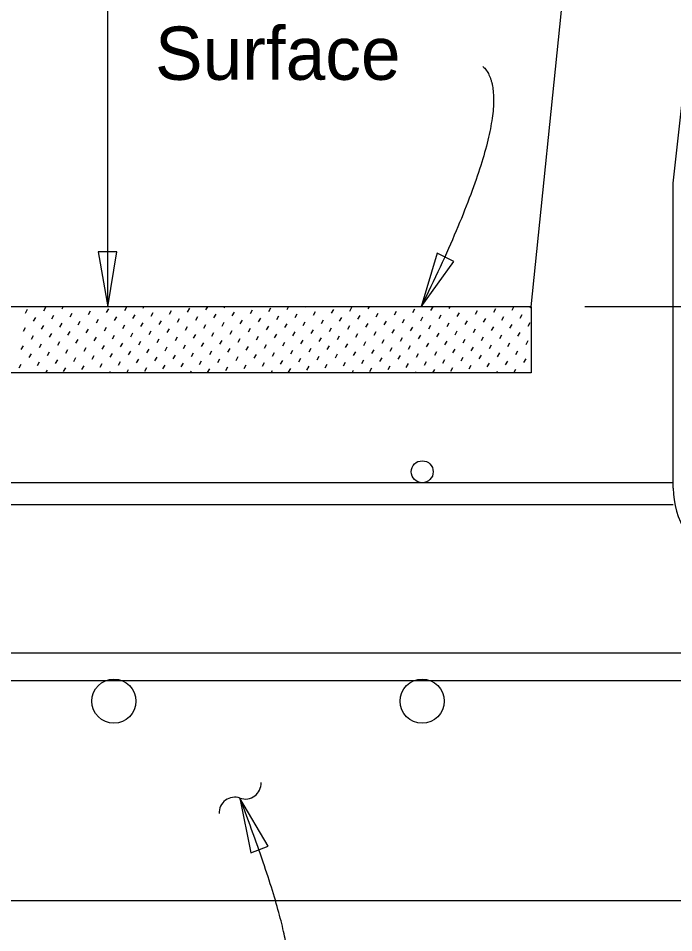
# Model space of a CAD drawing. Extents: x 130539.2 to 130573.7, y 88651.8 to 88671.1.
# Drawn here: x 130553.108 to 130554.348, y 88663.113 to 88664.844 of the extents above; entities that cross this region are included whole.
import ezdxf

# ---------------------------------------------------------------- set-up
doc = ezdxf.new("R2010")
doc.units = 0
for name, color, linetype in [('Dimension', 7, 'Continuous'), ('Miscellaneous', 7, 'Continuous'), ('Rebar', 7, 'Continuous'), ('Rebar_h', 7, 'Continuous'), ('TrafBarrierConc', 7, 'Continuous')]:
    doc.layers.add(name, color=color, linetype=linetype)

msp = doc.modelspace()

# ---------------------------------------------------------------- linework, layer by layer
at = {"layer": 'Dimension'}
msp.add_line((130553.277, 88664.2981), (130553.277, 88666.9647), dxfattribs=at)
for points in [[(130553.277, 88664.2981), (130553.2946, 88664.4022), (130553.2593, 88664.4022)], [(130553.8701, 88664.2981), (130553.9319, 88664.3837), (130553.9002, 88664.3993)], [(130553.5272, 88663.3673), (130553.5479, 88663.2638), (130553.5808, 88663.2764)]]:
    msp.add_lwpolyline(points, close=True, dxfattribs=at)
for centre, start, end in [((130553.5374, 88663.3956), 250.679, 2.4062), ((130553.5176, 88663.3394), 70.679, 182.4062)]:
    msp.add_arc(centre, 0.0298, start, end, dxfattribs=at)
for points in [[(130553.987, 88664.753), (130554.0597, 88664.6838), (130553.8701, 88664.2981)], [(130553.3789, 88662.9747), (130553.4967, 88662.9747), (130553.6188, 88662.9747), (130553.6188, 88663.1274), (130553.5272, 88663.3673)]]:
    msp.add_open_spline(points, degree=2, dxfattribs=at)
at = {"layer": 'Miscellaneous'}
for p, q in [((130554.0785, 88664.2981), (130552.1453, 88664.2981)), ((130553.156, 88664.2901), (130553.1601, 88664.2971)), ((130553.1906, 88664.2942), (130553.1928, 88664.2981)), ((130553.3094, 88664.2911), (130553.3135, 88664.2981)), ((130553.344, 88664.2951), (130553.3457, 88664.2981)), ((130553.4283, 88664.288), (130553.4324, 88664.295)), ((130553.4629, 88664.292), (130553.4664, 88664.2981)), ((130553.4974, 88664.2961), (130553.4986, 88664.2981)), ((130553.5818, 88664.2889), (130553.5858, 88664.2959)), ((130553.6163, 88664.293), (130553.6192, 88664.2981)), ((130553.6508, 88664.297), (130553.6514, 88664.2981)), ((130553.7352, 88664.2899), (130553.7392, 88664.2969)), ((130553.7697, 88664.2939), (130553.7721, 88664.2981)), ((130553.8043, 88664.298), (130553.8043, 88664.2981)), ((130553.8886, 88664.2909), (130553.8927, 88664.2979)), ((130553.9232, 88664.2949), (130553.925, 88664.2981)), ((130554.0075, 88664.2878), (130554.0115, 88664.2948)), ((130554.042, 88664.2918), (130554.0456, 88664.2981)), ((130554.0766, 88664.2959), (130554.0778, 88664.2981)), ((130553.1215, 88664.2861), (130553.1255, 88664.2931)), ((130553.1367, 88664.2708), (130553.1408, 88664.2778)), ((130553.1713, 88664.2749), (130553.1753, 88664.2819)), ((130553.2058, 88664.2789), (130553.2099, 88664.2859)), ((130553.2404, 88664.283), (130553.2444, 88664.29)), ((130553.2749, 88664.287), (130553.2789, 88664.294)), ((130553.2901, 88664.2718), (130553.2942, 88664.2788)), ((130553.3247, 88664.2758), (130553.3287, 88664.2828)), ((130553.3592, 88664.2799), (130553.3633, 88664.2869)), ((130553.3938, 88664.2839), (130553.3978, 88664.2909)), ((130553.4436, 88664.2727), (130553.4476, 88664.2797)), ((130553.4781, 88664.2768), (130553.4822, 88664.2838)), ((130553.5127, 88664.2808), (130553.5167, 88664.2878)), ((130553.5472, 88664.2849), (130553.5513, 88664.2919)), ((130553.597, 88664.2737), (130553.601, 88664.2807)), ((130553.6315, 88664.2777), (130553.6356, 88664.2847)), ((130553.6661, 88664.2818), (130553.6701, 88664.2888)), ((130553.7006, 88664.2858), (130553.7047, 88664.2928)), ((130553.7159, 88664.2706), (130553.7199, 88664.2776)), ((130553.7504, 88664.2747), (130553.7545, 88664.2816)), ((130553.785, 88664.2787), (130553.789, 88664.2857)), ((130553.8195, 88664.2828), (130553.8236, 88664.2897)), ((130553.8541, 88664.2868), (130553.8581, 88664.2938)), ((130553.8693, 88664.2716), (130553.8734, 88664.2786)), ((130553.9039, 88664.2756), (130553.9079, 88664.2826)), ((130553.9384, 88664.2797), (130553.9424, 88664.2867)), ((130553.9729, 88664.2837), (130553.977, 88664.2907)), ((130554.0227, 88664.2725), (130554.0268, 88664.2795)), ((130554.0573, 88664.2766), (130554.0613, 88664.2836)), ((130553.152, 88664.2556), (130553.156, 88664.2626)), ((130553.1865, 88664.2596), (130553.1906, 88664.2666)), ((130553.2211, 88664.2637), (130553.2251, 88664.2707)), ((130553.2556, 88664.2677), (130553.2596, 88664.2747)), ((130553.3054, 88664.2565), (130553.3094, 88664.2635)), ((130553.3399, 88664.2606), (130553.344, 88664.2676)), ((130553.3745, 88664.2646), (130553.3785, 88664.2716)), ((130553.409, 88664.2687), (130553.4131, 88664.2757)), ((130553.4243, 88664.2534), (130553.4283, 88664.2604)), ((130553.4588, 88664.2575), (130553.4629, 88664.2645)), ((130553.4934, 88664.2615), (130553.4974, 88664.2685)), ((130553.5279, 88664.2656), (130553.532, 88664.2726)), ((130553.5625, 88664.2696), (130553.5665, 88664.2766)), ((130553.5777, 88664.2544), (130553.5818, 88664.2614)), ((130553.6122, 88664.2584), (130553.6163, 88664.2654)), ((130553.6468, 88664.2625), (130553.6508, 88664.2695)), ((130553.6813, 88664.2665), (130553.6854, 88664.2735)), ((130553.7311, 88664.2554), (130553.7352, 88664.2623)), ((130553.7657, 88664.2594), (130553.7697, 88664.2664)), ((130553.8002, 88664.2635), (130553.8043, 88664.2705)), ((130553.8348, 88664.2675), (130553.8388, 88664.2745)), ((130553.8846, 88664.2563), (130553.8886, 88664.2633)), ((130553.9191, 88664.2604), (130553.9232, 88664.2674)), ((130553.9536, 88664.2644), (130553.9577, 88664.2714)), ((130553.9882, 88664.2685), (130553.9922, 88664.2755)), ((130554.0034, 88664.2532), (130554.0075, 88664.2602)), ((130554.038, 88664.2573), (130554.042, 88664.2643)), ((130554.0725, 88664.2613), (130554.0766, 88664.2683)), ((130553.1174, 88664.2515), (130553.1215, 88664.2585)), ((130553.1327, 88664.2363), (130553.1367, 88664.2433)), ((130553.1672, 88664.2403), (130553.1713, 88664.2473)), ((130553.2018, 88664.2444), (130553.2058, 88664.2514)), ((130553.2363, 88664.2484), (130553.2404, 88664.2554)), ((130553.2708, 88664.2525), (130553.2749, 88664.2595)), ((130553.2861, 88664.2372), (130553.2901, 88664.2442)), ((130553.3206, 88664.2413), (130553.3247, 88664.2483)), ((130553.3552, 88664.2453), (130553.3592, 88664.2523)), ((130553.3897, 88664.2494), (130553.3938, 88664.2564)), ((130553.4395, 88664.2382), (130553.4436, 88664.2452)), ((130553.4741, 88664.2422), (130553.4781, 88664.2492)), ((130553.5086, 88664.2463), (130553.5127, 88664.2533)), ((130553.5432, 88664.2503), (130553.5472, 88664.2573)), ((130553.5929, 88664.2391), (130553.597, 88664.2461)), ((130553.6275, 88664.2432), (130553.6315, 88664.2502)), ((130553.662, 88664.2472), (130553.6661, 88664.2542)), ((130553.6966, 88664.2513), (130553.7006, 88664.2583)), ((130553.7118, 88664.2361), (130553.7159, 88664.2431)), ((130553.7464, 88664.2401), (130553.7504, 88664.2471)), ((130553.7809, 88664.2442), (130553.785, 88664.2512)), ((130553.8155, 88664.2482), (130553.8195, 88664.2552)), ((130553.85, 88664.2523), (130553.8541, 88664.2593)), ((130553.8653, 88664.237), (130553.8693, 88664.244)), ((130553.8998, 88664.2411), (130553.9039, 88664.2481)), ((130553.9343, 88664.2451), (130553.9384, 88664.2521)), ((130553.9689, 88664.2492), (130553.9729, 88664.2562)), ((130554.0187, 88664.238), (130554.0227, 88664.245)), ((130554.0532, 88664.242), (130554.0573, 88664.249)), ((130553.1479, 88664.221), (130553.152, 88664.228)), ((130553.1825, 88664.2251), (130553.1865, 88664.2321)), ((130553.217, 88664.2291), (130553.2211, 88664.2361)), ((130553.2515, 88664.2332), (130553.2556, 88664.2402)), ((130553.3013, 88664.222), (130553.3054, 88664.229)), ((130553.3359, 88664.226), (130553.3399, 88664.233)), ((130553.3704, 88664.2301), (130553.3745, 88664.2371)), ((130553.405, 88664.2341), (130553.409, 88664.2411)), ((130553.4202, 88664.2189), (130553.4243, 88664.2259)), ((130553.4548, 88664.2229), (130553.4588, 88664.2299)), ((130553.4893, 88664.227), (130553.4934, 88664.234)), ((130553.5239, 88664.231), (130553.5279, 88664.238)), ((130553.5584, 88664.2351), (130553.5625, 88664.2421)), ((130553.5736, 88664.2198), (130553.5777, 88664.2268)), ((130553.6082, 88664.2239), (130553.6122, 88664.2309)), ((130553.6427, 88664.228), (130553.6468, 88664.2349)), ((130553.6773, 88664.232), (130553.6813, 88664.239)), ((130553.7271, 88664.2208), (130553.7311, 88664.2278)), ((130553.7616, 88664.2249), (130553.7657, 88664.2319)), ((130553.7962, 88664.2289), (130553.8002, 88664.2359)), ((130553.8307, 88664.233), (130553.8348, 88664.24)), ((130553.8805, 88664.2218), (130553.8846, 88664.2288)), ((130553.915, 88664.2258), (130553.9191, 88664.2328)), ((130553.9496, 88664.2299), (130553.9536, 88664.2369)), ((130553.9841, 88664.2339), (130553.9882, 88664.2409)), ((130553.9994, 88664.2187), (130554.0034, 88664.2257)), ((130554.0339, 88664.2227), (130554.038, 88664.2297)), ((130554.0685, 88664.2268), (130554.0725, 88664.2338)), ((130553.1134, 88664.217), (130553.1174, 88664.224)), ((130553.1286, 88664.2017), (130553.1327, 88664.2087)), ((130553.1632, 88664.2058), (130553.1672, 88664.2128)), ((130553.1977, 88664.2098), (130553.2018, 88664.2168)), ((130553.2322, 88664.2139), (130553.2363, 88664.2209)), ((130553.2668, 88664.2179), (130553.2708, 88664.2249)), ((130553.282, 88664.2027), (130553.2861, 88664.2097)), ((130553.3166, 88664.2067), (130553.3206, 88664.2137)), ((130553.3511, 88664.2108), (130553.3552, 88664.2178)), ((130553.3857, 88664.2148), (130553.3897, 88664.2218)), ((130553.4355, 88664.2036), (130553.4395, 88664.2106)), ((130553.47, 88664.2077), (130553.4741, 88664.2147)), ((130553.5046, 88664.2117), (130553.5086, 88664.2187)), ((130553.5391, 88664.2158), (130553.5432, 88664.2228)), ((130553.5889, 88664.2046), (130553.5929, 88664.2116)), ((130553.6234, 88664.2087), (130553.6275, 88664.2157)), ((130553.658, 88664.2127), (130553.662, 88664.2197)), ((130553.6925, 88664.2168), (130553.6966, 88664.2238)), ((130553.7078, 88664.2015), (130553.7118, 88664.2085)), ((130553.7423, 88664.2056), (130553.7464, 88664.2126)), ((130553.7769, 88664.2096), (130553.7809, 88664.2166)), ((130553.8114, 88664.2137), (130553.8155, 88664.2207)), ((130553.846, 88664.2177), (130553.85, 88664.2247)), ((130553.8612, 88664.2025), (130553.8653, 88664.2095)), ((130553.8958, 88664.2065), (130553.8998, 88664.2135)), ((130553.9303, 88664.2106), (130553.9343, 88664.2176)), ((130553.9648, 88664.2146), (130553.9689, 88664.2216)), ((130554.0146, 88664.2034), (130554.0187, 88664.2104)), ((130554.0492, 88664.2075), (130554.0532, 88664.2145)), ((130553.1439, 88664.1865), (130553.1479, 88664.1935)), ((130553.1784, 88664.1905), (130553.1825, 88664.1975)), ((130553.213, 88664.1946), (130553.217, 88664.2016)), ((130553.2475, 88664.1986), (130553.2515, 88664.2056)), ((130553.2973, 88664.1874), (130553.3013, 88664.1944)), ((130553.3318, 88664.1915), (130553.3359, 88664.1985)), ((130553.3664, 88664.1955), (130553.3704, 88664.2025)), ((130553.4009, 88664.1996), (130553.405, 88664.2066)), ((130553.4162, 88664.1843), (130553.4202, 88664.1913)), ((130553.4507, 88664.1884), (130553.4548, 88664.1954)), ((130553.4853, 88664.1924), (130553.4893, 88664.1994)), ((130553.5198, 88664.1965), (130553.5239, 88664.2035)), ((130553.5544, 88664.2006), (130553.5584, 88664.2075)), ((130553.5696, 88664.1853), (130553.5736, 88664.1923)), ((130553.6041, 88664.1894), (130553.6082, 88664.1964)), ((130553.6387, 88664.1934), (130553.6427, 88664.2004)), ((130553.6732, 88664.1975), (130553.6773, 88664.2045)), ((130553.723, 88664.1863), (130553.7271, 88664.1933)), ((130553.7576, 88664.1903), (130553.7616, 88664.1973)), ((130553.7921, 88664.1944), (130553.7962, 88664.2014)), ((130553.8267, 88664.1984), (130553.8307, 88664.2054)), ((130553.8765, 88664.1872), (130553.8805, 88664.1942)), ((130553.911, 88664.1913), (130553.915, 88664.1983)), ((130553.9455, 88664.1953), (130553.9496, 88664.2023)), ((130553.9801, 88664.1994), (130553.9841, 88664.2064)), ((130553.9953, 88664.1841), (130553.9994, 88664.1911)), ((130554.0299, 88664.1882), (130554.0339, 88664.1952)), ((130554.0644, 88664.1922), (130554.0685, 88664.1992)), ((130553.1093, 88664.1824), (130553.1134, 88664.1894)), ((130553.128, 88664.1731), (130553.1286, 88664.1742)), ((130553.1602, 88664.1731), (130553.1632, 88664.1782)), ((130553.1937, 88664.1753), (130553.1977, 88664.1823)), ((130553.2282, 88664.1793), (130553.2322, 88664.1863)), ((130553.2627, 88664.1834), (130553.2668, 88664.1904)), ((130553.2808, 88664.1731), (130553.282, 88664.1751)), ((130553.313, 88664.1731), (130553.3166, 88664.1792)), ((130553.3471, 88664.1762), (130553.3511, 88664.1832)), ((130553.3816, 88664.1803), (130553.3857, 88664.1873)), ((130553.4337, 88664.1731), (130553.4355, 88664.1761)), ((130553.466, 88664.1732), (130553.47, 88664.1801)), ((130553.5005, 88664.1772), (130553.5046, 88664.1842)), ((130553.5351, 88664.1813), (130553.5391, 88664.1883)), ((130553.5866, 88664.1731), (130553.5889, 88664.1771)), ((130553.6194, 88664.1741), (130553.6234, 88664.1811)), ((130553.6539, 88664.1782), (130553.658, 88664.1852)), ((130553.6885, 88664.1822), (130553.6925, 88664.1892)), ((130553.7073, 88664.1731), (130553.7078, 88664.174)), ((130553.7395, 88664.1731), (130553.7423, 88664.178)), ((130553.7728, 88664.1751), (130553.7769, 88664.1821)), ((130553.8074, 88664.1791), (130553.8114, 88664.1861)), ((130553.8419, 88664.1832), (130553.846, 88664.1902)), ((130553.8601, 88664.1731), (130553.8612, 88664.1749)), ((130553.8923, 88664.1731), (130553.8958, 88664.179)), ((130553.9262, 88664.176), (130553.9303, 88664.183)), ((130553.9608, 88664.1801), (130553.9648, 88664.1871)), ((130554.013, 88664.1731), (130554.0146, 88664.1759)), ((130554.0452, 88664.1731), (130554.0492, 88664.1799))]:
    msp.add_line(p, q, dxfattribs=at)
at = {"layer": 'Rebar'}
for p, q in [((130554.3471, 88664.5318), (130554.5805, 88666.6418)), ((130554.3471, 88663.9542), (130554.3471, 88664.5318)), ((130554.3471, 88663.9543), (130554.3471, 88664.498))]:
    msp.add_line(p, q, dxfattribs=at)
msp.add_arc((130554.5033, 88663.9542), 0.1562, 180, 243.8961, dxfattribs=at)
at = {"layer": 'Rebar_h'}
for p, q in [((130554.3471, 88663.9647), (130552.8358, 88663.9647)), ((130554.3471, 88663.923), (130552.8162, 88663.923)), ((130555.1221, 88663.6418), (130552.8271, 88663.6418)), ((130555.1221, 88663.5897), (130552.8314, 88663.5897))]:
    msp.add_line(p, q, dxfattribs=at)
for centre, radius in [((130553.8721, 88663.9855), 0.0208), ((130553.2888, 88663.5512), 0.0417), ((130553.8721, 88663.5512), 0.0417)]:
    msp.add_circle(centre, radius, dxfattribs=at)
at = {"layer": 'TrafBarrierConc'}
for p, q in [((130554.0785, 88664.2981), (130554.3449, 88666.9025)), ((130554.0785, 88664.2981), (130554.0785, 88664.1731)), ((130555.042, 88664.2981), (130554.1795, 88664.2981)), ((130554.0785, 88664.1731), (130552.8142, 88664.1731)), ((130555.2887, 88663.1731), (130552.1453, 88663.1731))]:
    msp.add_line(p, q, dxfattribs=at)

# ---------------------------------------------------------------- texts
at = {"layer": 'Dimension'}
msp.add_text('Surface', height=0.1008, dxfattribs=at).set_placement((130553.3666, 88664.7277))

doc.saveas('drawing.dxf')
